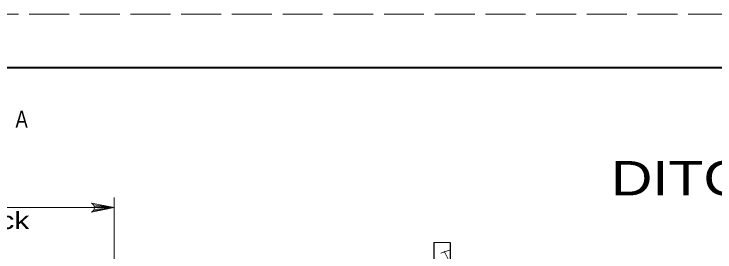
# Model space of a CAD drawing. Extents: x 1083.1 to 1117.1, y 672.5 to 716.5.
# Drawn here: x 1093.96 to 1100.48, y 714.29 to 716.51 of the extents above; entities that cross this region are included whole.
import ezdxf
from ezdxf.enums import TextEntityAlignment as Align

# ---------------------------------------------------------------- set-up
doc = ezdxf.new("R2010")
doc.units = 0
doc.header["$LTSCALE"] = 0.062
doc.linetypes.add('LONG_DASHED', pattern=[7.5, 6, -1.5])
doc.layers.add('1', color=7, linetype='Continuous', lineweight=13)

msp = doc.modelspace()

# ---------------------------------------------------------------- linework, layer by layer
at = {"layer": '1', "lineweight": 25}
for p, q in [((1085.12642, 716.00825), (1116.62642, 716.00825)), ((1097.8655, 714.37808), (1097.8655, 712.90883)), ((1098.01842, 714.37808), (1098.01842, 712.98975))]:
    msp.add_line(p, q, dxfattribs=at)
at = {"layer": '1'}
for p, q in [((1094.89058, 712.97825), (1094.89058, 714.79783)), ((1094.89058, 714.70292), (1091.49067, 714.70292)), ((1094.69475, 714.673), (1094.89058, 714.70292)), ((1094.69708, 714.73), (1094.89058, 714.70292)), ((1094.70217, 714.6855), (1094.89058, 714.70292)), ((1094.70358, 714.71658), (1094.89058, 714.70292)), ((1094.70558, 714.70292), (1094.89058, 714.70292)), ((1094.71217, 714.70292), (1094.88792, 714.70292)), ((1098.01842, 714.37808), (1097.8655, 714.37808)), ((1097.9305, 714.27833), (1098.0105, 714.30583)), ((1097.96108, 714.29708), (1098.01183, 714.19808))]:
    msp.add_line(p, q, dxfattribs=at)
at = {"layer": '1', "linetype": 'LONG_DASHED'}
msp.add_lwpolyline([(1083.12642, 694.50825), (1117.12642, 694.50825), (1117.12642, 716.50825), (1083.12642, 716.50825)], close=True, dxfattribs=at)
at = {"layer": '1', "lineweight": 40}
msp.add_lwpolyline([(1085.12642, 716.00825), (1116.62642, 716.00825), (1116.62642, 695.00825), (1085.12642, 695.00825)], close=True, dxfattribs=at)
msp.add_lwpolyline([(1085.12642, 716.00825), (1116.62642, 716.00825), (1116.62642, 695.00825), (1085.12642, 695.00825)], close=True, dxfattribs=at)
at = {"layer": '1'}
msp.add_lwpolyline([(1094.67683, 714.66017), (1094.89058, 714.70292), (1094.67683, 714.74567)], dxfattribs=at)
msp.add_arc((1094.65959, 714.70294), 0.04613, 292.08605, 67.91218, dxfattribs=at)

# ---------------------------------------------------------------- texts
at = {"layer": '1', "width": 0.8}
msp.add_text('A', height=0.16, dxfattribs=at).set_placement((1093.97008, 715.44817))
at = {"layer": '1'}
for s, height, width, p in [('DITCH CHECKS', 0.32, 1.25, (1101.521, 714.81758)), ('width for Rock', 0.16, 1.3, (1093.21692, 714.50383))]:
    msp.add_text(s, height=height, dxfattribs=dict(at, width=width)).set_placement(p, align=Align.CENTER)

doc.saveas('drawing.dxf')
